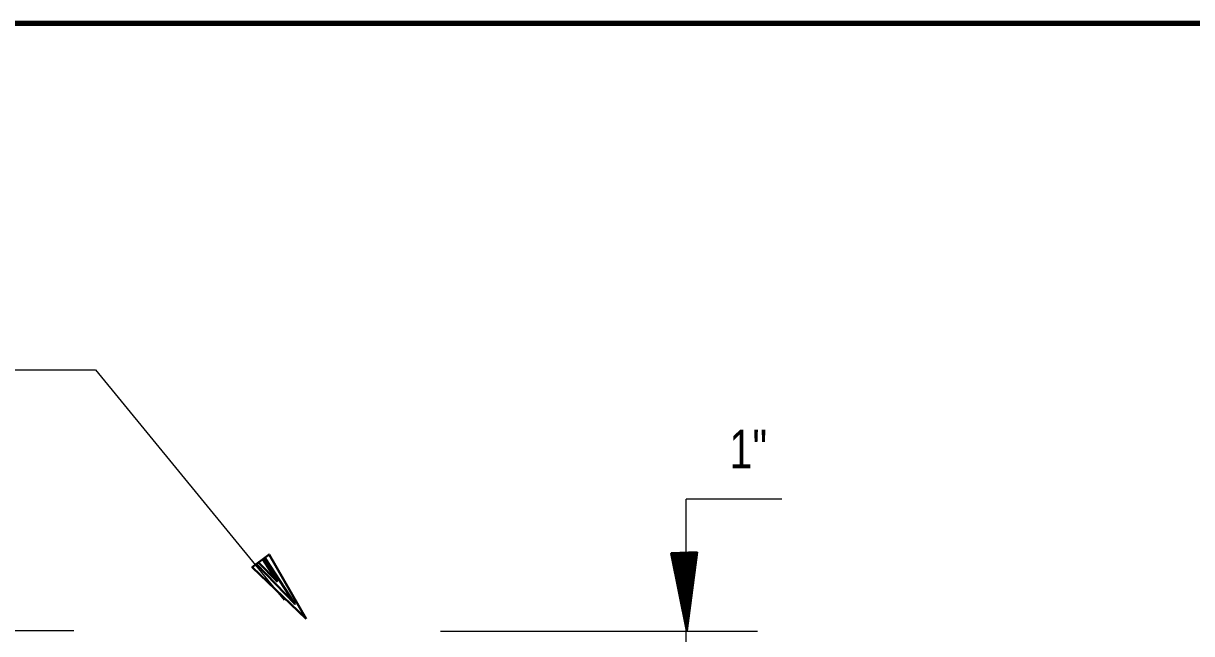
# Model space of a CAD drawing. Extents: x 856.9 to 891.7, y -2278.5 to -2254.7.
# Drawn here: x 864.144 to 868.027, y -2258.193 to -2256.163 of the extents above; entities that cross this region are included whole.
import ezdxf

# ---------------------------------------------------------------- set-up
doc = ezdxf.new("R2010")
doc.units = 0
doc.header["$LTSCALE"] = 0.051
doc.layers.add('1', color=7, linetype='Continuous', lineweight=70)
doc.layers.add('3', color=7, linetype='Continuous', lineweight=40)

msp = doc.modelspace()

# ---------------------------------------------------------------- hatches: boundary and pattern name
at = {"layer": '3'}
for points in [[(866.38433, -2257.9225), (866.29767, -2257.92542), (866.34983, -2258.18383), (866.34983, -2258.18383)], [(866.38, -2257.92375), (866.302, -2257.9265), (866.349, -2258.15908), (866.349, -2258.15908)], [(866.37608, -2257.925), (866.306, -2257.92733), (866.34825, -2258.13667), (866.34825, -2258.13667)], [(866.37267, -2257.926), (866.30958, -2257.92817), (866.34758, -2258.11667), (866.34758, -2258.11667)], [(866.36967, -2257.92692), (866.31283, -2257.92883), (866.347, -2258.09858), (866.347, -2258.09858)], [(866.36675, -2257.928), (866.31567, -2257.92958), (866.3465, -2258.08233), (866.3465, -2258.08233)], [(866.36417, -2257.92867), (866.31825, -2257.93017), (866.346, -2258.06758), (866.346, -2258.06758)], [(866.362, -2257.9295), (866.3205, -2257.93075), (866.3455, -2258.05433), (866.3455, -2258.05433)], [(866.36, -2257.92992), (866.32258, -2257.93125), (866.345, -2258.04258), (866.345, -2258.04258)], [(866.358, -2257.93067), (866.32433, -2257.93183), (866.34467, -2258.03175), (866.34467, -2258.03175)], [(866.3565, -2257.93108), (866.32617, -2257.93217), (866.34442, -2258.02217), (866.34442, -2258.02217)], [(866.35492, -2257.93158), (866.32775, -2257.93258), (866.344, -2258.01358), (866.344, -2258.01358)], [(866.35358, -2257.932), (866.32908, -2257.93283), (866.34375, -2258.00567), (866.34375, -2258.00567)], [(866.35233, -2257.93258), (866.33025, -2257.93308), (866.34358, -2257.99875), (866.34358, -2257.99875)], [(866.35125, -2257.93275), (866.33142, -2257.93342), (866.34342, -2257.9925), (866.34342, -2257.9925)], [(866.35025, -2257.93317), (866.33242, -2257.93358), (866.34308, -2257.98683), (866.34308, -2257.98683)], [(866.34933, -2257.93333), (866.33325, -2257.93392), (866.34292, -2257.98175), (866.34292, -2257.98175)], [(866.3485, -2257.9335), (866.33408, -2257.93408), (866.34275, -2257.97717), (866.34275, -2257.97717)], [(866.34808, -2257.93392), (866.33492, -2257.93417), (866.34275, -2257.97308), (866.34275, -2257.97308)], [(866.3475, -2257.93408), (866.33567, -2257.9345), (866.34267, -2257.96942), (866.34267, -2257.96942)], [(866.347, -2257.93442), (866.33642, -2257.93483), (866.34283, -2257.96617), (866.34283, -2257.96617)], [(866.34642, -2257.93442), (866.337, -2257.93483), (866.34267, -2257.96308), (866.34267, -2257.96308)], [(866.34592, -2257.93458), (866.33742, -2257.93492), (866.34242, -2257.96033), (866.34242, -2257.96033)], [(866.3455, -2257.93483), (866.33792, -2257.935), (866.3425, -2257.958), (866.3425, -2257.958)]]:
    msp.add_hatch(color=256, dxfattribs=at).paths.add_polyline_path(points)

# ---------------------------------------------------------------- linework, layer by layer
at = {"layer": '1', "lineweight": 25}
for p, q in [((862.22183, -2257.31533), (864.38367, -2257.31533)), ((864.38367, -2257.31533), (865.01175, -2258.08192)), ((866.347, -2260.11883), (866.347, -2257.74608)), ((866.66567, -2257.74608), (866.347, -2257.74608)), ((863.36417, -2258.18292), (864.31233, -2258.18292)), ((866.58492, -2258.18633), (865.53142, -2258.18633))]:
    msp.add_line(p, q, dxfattribs=at)
at = {"layer": '1', "lineweight": 40}
msp.add_lwpolyline([(865.08408, -2258.14367), (864.96142, -2257.92958), (864.90525, -2257.97208)], close=True, dxfattribs=at)
for points in [[(864.94725, -2257.94042), (865.04692, -2258.09433), (864.91967, -2257.9615)], [(864.93992, -2257.94558), (864.98758, -2258.01917), (864.9265, -2257.95592)]]:
    msp.add_lwpolyline(points, dxfattribs=at)
at = {"layer": '3', "lineweight": 158}
msp.add_line((891.2, -2256.16333), (858.7, -2256.16333), dxfattribs=at)
at = {"layer": '3'}
for points in [[(866.38433, -2257.9225), (866.29767, -2257.92542), (866.34983, -2258.18383), (866.34983, -2258.18383)], [(866.38, -2257.92375), (866.302, -2257.9265), (866.349, -2258.15908), (866.349, -2258.15908)], [(866.37608, -2257.925), (866.306, -2257.92733), (866.34825, -2258.13667), (866.34825, -2258.13667)], [(866.37267, -2257.926), (866.30958, -2257.92817), (866.34758, -2258.11667), (866.34758, -2258.11667)], [(866.36967, -2257.92692), (866.31283, -2257.92883), (866.347, -2258.09858), (866.347, -2258.09858)], [(866.36675, -2257.928), (866.31567, -2257.92958), (866.3465, -2258.08233), (866.3465, -2258.08233)], [(866.36417, -2257.92867), (866.31825, -2257.93017), (866.346, -2258.06758), (866.346, -2258.06758)], [(866.362, -2257.9295), (866.3205, -2257.93075), (866.3455, -2258.05433), (866.3455, -2258.05433)], [(866.36, -2257.92992), (866.32258, -2257.93125), (866.345, -2258.04258), (866.345, -2258.04258)], [(866.358, -2257.93067), (866.32433, -2257.93183), (866.34467, -2258.03175), (866.34467, -2258.03175)], [(866.3565, -2257.93108), (866.32617, -2257.93217), (866.34442, -2258.02217), (866.34442, -2258.02217)], [(866.35492, -2257.93158), (866.32775, -2257.93258), (866.344, -2258.01358), (866.344, -2258.01358)], [(866.35358, -2257.932), (866.32908, -2257.93283), (866.34375, -2258.00567), (866.34375, -2258.00567)], [(866.35233, -2257.93258), (866.33025, -2257.93308), (866.34358, -2257.99875), (866.34358, -2257.99875)], [(866.35125, -2257.93275), (866.33142, -2257.93342), (866.34342, -2257.9925), (866.34342, -2257.9925)], [(866.35025, -2257.93317), (866.33242, -2257.93358), (866.34308, -2257.98683), (866.34308, -2257.98683)], [(866.34933, -2257.93333), (866.33325, -2257.93392), (866.34292, -2257.98175), (866.34292, -2257.98175)], [(866.3485, -2257.9335), (866.33408, -2257.93408), (866.34275, -2257.97717), (866.34275, -2257.97717)], [(866.34808, -2257.93392), (866.33492, -2257.93417), (866.34275, -2257.97308), (866.34275, -2257.97308)], [(866.3475, -2257.93408), (866.33567, -2257.9345), (866.34267, -2257.96942), (866.34267, -2257.96942)], [(866.347, -2257.93442), (866.33642, -2257.93483), (866.34283, -2257.96617), (866.34283, -2257.96617)], [(866.34642, -2257.93442), (866.337, -2257.93483), (866.34267, -2257.96308), (866.34267, -2257.96308)], [(866.34592, -2257.93458), (866.33742, -2257.93492), (866.34242, -2257.96033), (866.34242, -2257.96033)], [(866.3455, -2257.93483), (866.33792, -2257.935), (866.3425, -2257.958), (866.3425, -2257.958)]]:
    msp.add_lwpolyline(points, close=True, dxfattribs=at)

# ---------------------------------------------------------------- texts
at = {"layer": '1', "width": 0.8}
msp.add_text('1"', height=0.1286, dxfattribs=at).set_placement((866.49117, -2257.64342))

doc.saveas('drawing.dxf')
